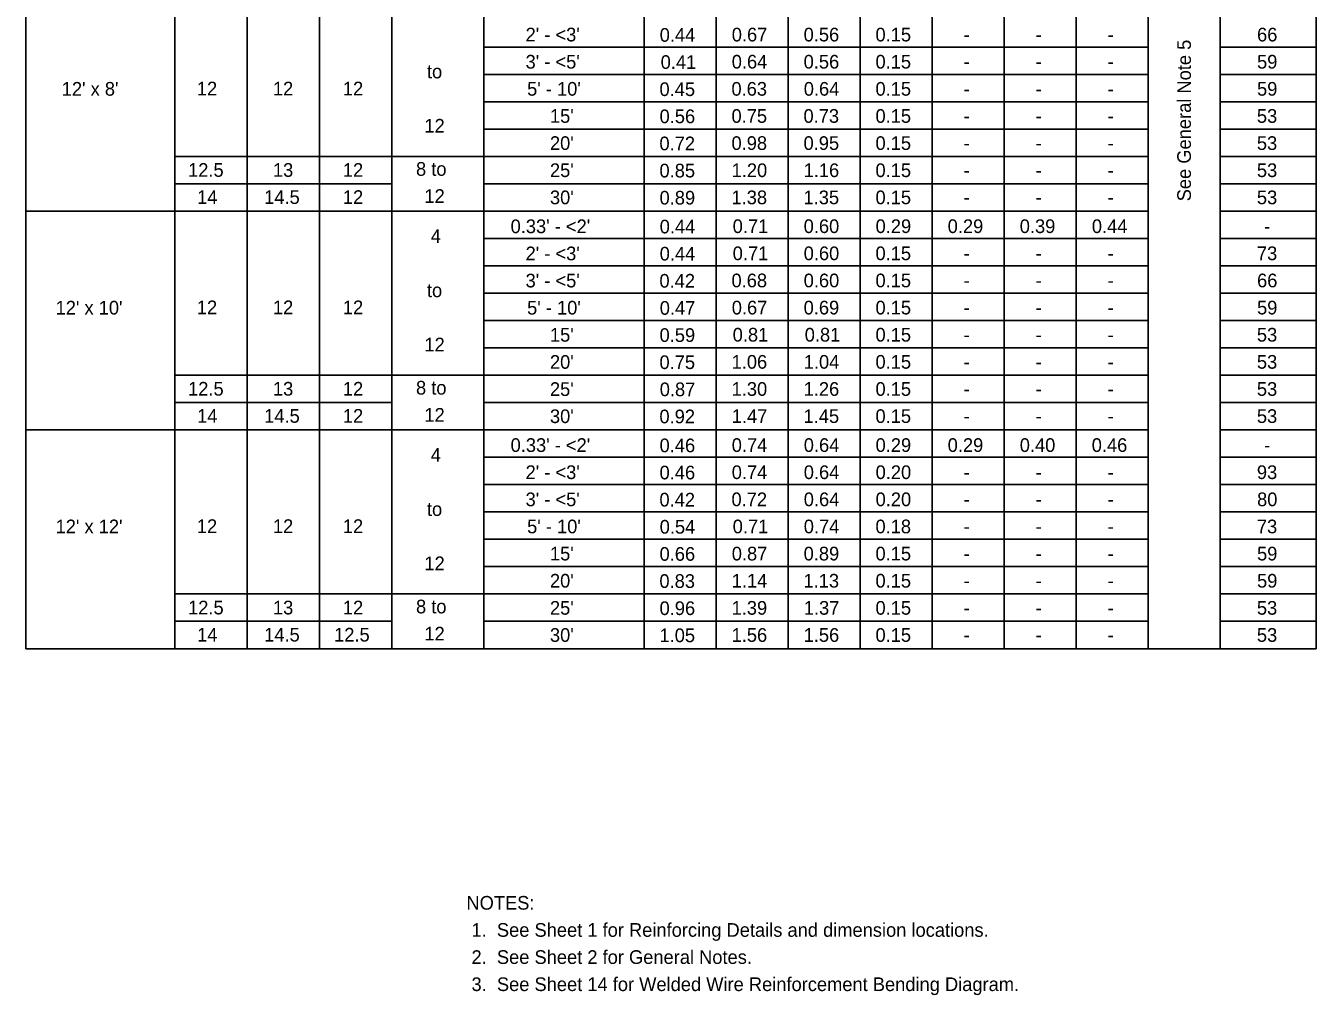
# Model space of a CAD drawing. Extents: x 10351.18 to 10353.4, y 76399.49 to 76400.59.
# Drawn here: x 10351.832 to 10352.427, y 76399.766 to 76400.212 of the extents above; entities that cross this region are included whole.
import ezdxf

# ---------------------------------------------------------------- set-up
doc = ezdxf.new("R2010")
doc.units = 0
doc.layers.add('AdhocPoint_dp', color=7, linetype='Continuous')
doc.layers.add('PlotBorder_dp', color=7, linetype='Continuous')

msp = doc.modelspace()

# ---------------------------------------------------------------- linework, layer by layer
at = {"layer": 'PlotBorder_dp'}
for p, q in [((10351.83244, 76400.49971), (10351.83244, 76399.92549)), ((10352.42718, 76400.49971), (10352.42718, 76399.92549)), ((10351.90108, 76400.47984), (10351.90108, 76399.92549)), ((10352.04352, 76400.47984), (10352.04352, 76399.92549)), ((10352.1174, 76400.47984), (10352.1174, 76399.92549)), ((10352.38299, 76400.47984), (10352.38299, 76399.92549)), ((10351.93444, 76400.46724), (10351.93444, 76399.92549)), ((10351.9678, 76400.46724), (10351.9678, 76399.92549)), ((10352.00116, 76400.46724), (10352.00116, 76399.92549)), ((10352.1506, 76400.44209), (10352.1506, 76399.92549)), ((10352.1838, 76400.44209), (10352.1838, 76399.92549)), ((10352.217, 76400.44209), (10352.217, 76399.92549)), ((10352.2502, 76400.44209), (10352.2502, 76399.92549)), ((10352.28339, 76400.44209), (10352.28339, 76399.92549)), ((10352.28339, 76400.44209), (10352.28339, 76399.92549)), ((10352.31659, 76400.44209), (10352.31659, 76399.92549)), ((10352.34979, 76400.44209), (10352.34979, 76399.92549)), ((10352.04352, 76400.20269), (10352.34979, 76400.20269)), ((10352.38299, 76400.20269), (10352.42718, 76400.20269)), ((10352.04352, 76400.19009), (10352.34979, 76400.19009)), ((10352.38299, 76400.19009), (10352.42718, 76400.19009)), ((10352.04352, 76400.17749), (10352.34979, 76400.17749)), ((10352.38299, 76400.17749), (10352.42718, 76400.17749)), ((10352.04352, 76400.16489), (10352.34979, 76400.16489)), ((10352.38299, 76400.16489), (10352.42718, 76400.16489)), ((10352.04352, 76400.15229), (10351.90108, 76400.15229)), ((10352.04352, 76400.15229), (10352.34979, 76400.15229)), ((10352.38299, 76400.15229), (10352.42718, 76400.15229)), ((10352.00116, 76400.13969), (10351.90108, 76400.13969)), ((10352.04352, 76400.13969), (10352.34979, 76400.13969)), ((10352.38299, 76400.13969), (10352.42718, 76400.13969)), ((10351.83244, 76400.12709), (10352.34979, 76400.12709)), ((10352.04414, 76400.12709), (10352.11631, 76400.12709)), ((10352.38299, 76400.12709), (10352.42718, 76400.12709)), ((10352.04352, 76400.11449), (10352.34979, 76400.11449)), ((10352.38299, 76400.11449), (10352.42718, 76400.11449)), ((10352.04352, 76400.10189), (10352.34979, 76400.10189)), ((10352.38299, 76400.10189), (10352.42718, 76400.10189)), ((10352.04352, 76400.08929), (10352.34979, 76400.08929)), ((10352.38299, 76400.08929), (10352.42718, 76400.08929)), ((10352.04352, 76400.07669), (10352.34979, 76400.07669)), ((10352.38299, 76400.07669), (10352.42718, 76400.07669)), ((10352.04352, 76400.06409), (10352.34979, 76400.06409)), ((10352.38299, 76400.06409), (10352.42718, 76400.06409)), ((10352.04352, 76400.05149), (10351.90108, 76400.05149)), ((10352.04352, 76400.05149), (10352.34979, 76400.05149)), ((10352.38299, 76400.05149), (10352.42718, 76400.05149)), ((10352.00116, 76400.03889), (10351.90108, 76400.03889)), ((10352.04352, 76400.03889), (10352.34979, 76400.03889)), ((10352.38299, 76400.03889), (10352.42718, 76400.03889)), ((10351.83244, 76400.02629), (10352.34979, 76400.02629)), ((10352.04414, 76400.02629), (10352.11631, 76400.02629)), ((10352.38299, 76400.02629), (10352.42718, 76400.02629)), ((10352.04352, 76400.01369), (10352.34979, 76400.01369)), ((10352.38299, 76400.01369), (10352.42718, 76400.01369)), ((10352.04352, 76400.00109), (10352.34979, 76400.00109)), ((10352.38299, 76400.00109), (10352.42718, 76400.00109)), ((10352.04352, 76399.98849), (10352.34979, 76399.98849)), ((10352.38299, 76399.98849), (10352.42718, 76399.98849)), ((10352.04352, 76399.97589), (10352.34979, 76399.97589)), ((10352.38299, 76399.97589), (10352.42718, 76399.97589)), ((10352.04352, 76399.96329), (10352.34979, 76399.96329)), ((10352.38299, 76399.96329), (10352.42718, 76399.96329)), ((10352.04352, 76399.95069), (10351.90108, 76399.95069)), ((10352.04352, 76399.95069), (10352.34979, 76399.95069)), ((10352.38299, 76399.95069), (10352.42718, 76399.95069)), ((10352.00116, 76399.93809), (10351.90108, 76399.93809)), ((10352.04352, 76399.93809), (10352.34979, 76399.93809)), ((10352.38299, 76399.93809), (10352.42718, 76399.93809)), ((10351.83244, 76399.92549), (10352.42718, 76399.92549)), ((10352.04414, 76399.92549), (10352.11631, 76399.92549)), ((10352.04414, 76399.92549), (10352.11631, 76399.92549)), ((10352.04414, 76399.92549), (10352.11631, 76399.92549))]:
    msp.add_line(p, q, dxfattribs=at)

# ---------------------------------------------------------------- texts
at = {"layer": 'AdhocPoint_dp'}
msp.add_text('See General Note 5', height=0.0063, rotation=90, dxfattribs=at).set_placement((10352.36944, 76400.13159))
at = {"layer": 'PlotBorder_dp'}
for s, p in [("2' - <3'", (10352.06278, 76400.20526)), ('0.44', (10352.1246, 76400.2051)), ('0.67', (10352.15782, 76400.20526)), ('0.56', (10352.19094, 76400.20526)), ('0.15', (10352.22406, 76400.20526)), ('66', (10352.39992, 76400.20526)), ('-', (10352.26467, 76400.20526)), ('-', (10352.29788, 76400.20526)), ('-', (10352.33106, 76400.20526)), ("3' - <5'", (10352.06278, 76400.19276)), ('0.41', (10352.12504, 76400.1926)), ('0.64', (10352.1578, 76400.19276)), ('0.56', (10352.19094, 76400.19276)), ('0.15', (10352.22406, 76400.19276)), ('59', (10352.39992, 76400.19276)), ('to', (10352.01732, 76400.18825)), ('-', (10352.26467, 76400.19276)), ('-', (10352.29788, 76400.19276)), ('-', (10352.33106, 76400.19276)), ("12' x 8'", (10351.849, 76400.18026)), ('12', (10351.91127, 76400.18038)), ('12', (10351.94634, 76400.18038)), ('12', (10351.97858, 76400.18038)), ("5' - 10'", (10352.06349, 76400.18026)), ('0.45', (10352.1245, 76400.1801)), ('0.63', (10352.15767, 76400.18026)), ('0.64', (10352.191, 76400.18026)), ('0.15', (10352.22406, 76400.18026)), ('59', (10352.39992, 76400.18026)), ('-', (10352.26467, 76400.18026)), ('-', (10352.29788, 76400.18026)), ('-', (10352.33106, 76400.18026)), ("15'", (10352.07401, 76400.16776)), ('0.56', (10352.12454, 76400.1676)), ('0.75', (10352.1577, 76400.16776)), ('0.73', (10352.19087, 76400.16776)), ('0.15', (10352.22406, 76400.16776)), ('53', (10352.39985, 76400.16776)), ('12', (10352.01615, 76400.16325)), ('-', (10352.26467, 76400.16776)), ('-', (10352.29788, 76400.16776)), ('-', (10352.33106, 76400.16776)), ("20'", (10352.07401, 76400.15526)), ('0.98', (10352.15769, 76400.15526)), ('0.95', (10352.1909, 76400.15526)), ('0.15', (10352.22406, 76400.15526)), ('53', (10352.39985, 76400.15526)), ('0.72', (10352.12448, 76400.1551)), ('-', (10352.26467, 76400.15526)), ('-', (10352.29788, 76400.15526)), ('-', (10352.33106, 76400.15526)), ('8 to', (10352.01228, 76400.14336)), ('12.5', (10351.90723, 76400.14288)), ('13', (10351.94634, 76400.14288)), ('12', (10351.97858, 76400.14288)), ("25'", (10352.07401, 76400.14276)), ('0.85', (10352.1245, 76400.1426)), ('1.20', (10352.15775, 76400.14276)), ('1.16', (10352.19094, 76400.14276)), ('0.15', (10352.22406, 76400.14276)), ('-', (10352.26467, 76400.14276)), ('-', (10352.29788, 76400.14276)), ('-', (10352.33106, 76400.14276)), ('53', (10352.39985, 76400.14276)), ('14', (10351.9114, 76400.13038)), ('14.5', (10351.9423, 76400.13038)), ('12', (10351.97858, 76400.13038)), ('12', (10352.01615, 76400.13086)), ("30'", (10352.07401, 76400.13026)), ('0.89', (10352.12454, 76400.1301)), ('1.38', (10352.15769, 76400.13026)), ('1.35', (10352.1909, 76400.13026)), ('0.15', (10352.22406, 76400.13026)), ('-', (10352.26467, 76400.13026)), ('-', (10352.29788, 76400.13026)), ('-', (10352.33106, 76400.13026)), ('53', (10352.39985, 76400.13026)), ("0.33' - <2'", (10352.05588, 76400.11693)), ('0.44', (10352.1246, 76400.11682)), ('0.71', (10352.15824, 76400.11698)), ('0.60', (10352.19096, 76400.11698)), ('0.29', (10352.2241, 76400.11698)), ('0.29', (10352.25733, 76400.11698)), ('0.39', (10352.29054, 76400.11698)), ('0.44', (10352.32378, 76400.11698)), ('4', (10352.0191, 76400.11245)), ('-', (10352.40319, 76400.11698)), ("2' - <3'", (10352.06278, 76400.10443)), ('0.44', (10352.1246, 76400.10432)), ('0.71', (10352.15824, 76400.10448)), ('0.60', (10352.19096, 76400.10448)), ('0.15', (10352.22406, 76400.10448)), ('73', (10352.39985, 76400.10448)), ('-', (10352.26467, 76400.10448)), ('-', (10352.29788, 76400.10448)), ('-', (10352.33106, 76400.10448)), ("3' - <5'", (10352.06278, 76400.09193)), ('0.42', (10352.12448, 76400.09182)), ('0.68', (10352.15769, 76400.09198)), ('0.60', (10352.19096, 76400.09198)), ('0.15', (10352.22406, 76400.09198)), ('66', (10352.39992, 76400.09198)), ('to', (10352.01732, 76400.08745)), ('-', (10352.26467, 76400.09198)), ('-', (10352.29788, 76400.09198)), ('-', (10352.33106, 76400.09198)), ("12' x 10'", (10351.84617, 76400.07943)), ('12', (10351.91127, 76400.07958)), ('12', (10351.94634, 76400.07958)), ('12', (10351.97858, 76400.07958)), ("5' - 10'", (10352.06349, 76400.07943)), ('0.47', (10352.12462, 76400.07932)), ('0.67', (10352.15782, 76400.07948)), ('0.69', (10352.19094, 76400.07948)), ('0.15', (10352.22406, 76400.07948)), ('59', (10352.39992, 76400.07948)), ('-', (10352.26467, 76400.07948)), ('-', (10352.29788, 76400.07948)), ('-', (10352.33106, 76400.07948)), ("15'", (10352.07401, 76400.06693)), ('0.59', (10352.12454, 76400.06682)), ('0.81', (10352.15824, 76400.06698)), ('0.81', (10352.19144, 76400.06698)), ('0.15', (10352.22406, 76400.06698)), ('53', (10352.39985, 76400.06698)), ('12', (10352.01615, 76400.06245)), ('-', (10352.26467, 76400.06698)), ('-', (10352.29788, 76400.06698)), ('-', (10352.33106, 76400.06698)), ("20'", (10352.07401, 76400.05443)), ('0.75', (10352.1245, 76400.05432)), ('1.06', (10352.15774, 76400.05448)), ('1.04', (10352.191, 76400.05448)), ('0.15', (10352.22406, 76400.05448)), ('53', (10352.39985, 76400.05448)), ('-', (10352.26467, 76400.05448)), ('-', (10352.29788, 76400.05448)), ('-', (10352.33106, 76400.05448)), ('8 to', (10352.01228, 76400.04256)), ('12.5', (10351.90723, 76400.04208)), ('13', (10351.94634, 76400.04208)), ('12', (10351.97858, 76400.04208)), ("25'", (10352.07401, 76400.04193)), ('0.87', (10352.12462, 76400.04182)), ('1.30', (10352.15775, 76400.04198)), ('1.26', (10352.19094, 76400.04198)), ('0.15', (10352.22406, 76400.04198)), ('-', (10352.26467, 76400.04198)), ('-', (10352.29788, 76400.04198)), ('-', (10352.33106, 76400.04198)), ('53', (10352.39985, 76400.04198)), ('14', (10351.9114, 76400.02958)), ('14.5', (10351.9423, 76400.02958)), ('12', (10351.97858, 76400.02958)), ('12', (10352.01615, 76400.03006)), ("30'", (10352.07401, 76400.02943)), ('0.92', (10352.12448, 76400.02932)), ('1.47', (10352.15782, 76400.02948)), ('1.45', (10352.1909, 76400.02948)), ('0.15', (10352.22406, 76400.02948)), ('-', (10352.26467, 76400.02948)), ('-', (10352.29788, 76400.02948)), ('-', (10352.33106, 76400.02948)), ('53', (10352.39985, 76400.02948)), ("0.33' - <2'", (10352.05588, 76400.01614)), ('0.46', (10352.12454, 76400.01599)), ('0.74', (10352.1578, 76400.01614)), ('0.64', (10352.191, 76400.01614)), ('0.29', (10352.2241, 76400.01614)), ('0.29', (10352.25733, 76400.01614)), ('0.40', (10352.29055, 76400.01614)), ('0.46', (10352.32372, 76400.01614)), ('-', (10352.40319, 76400.01614)), ('4', (10352.0191, 76400.01165)), ("2' - <3'", (10352.06278, 76400.00364)), ('0.46', (10352.12454, 76400.00349)), ('0.74', (10352.1578, 76400.00364)), ('0.64', (10352.191, 76400.00364)), ('0.20', (10352.22411, 76400.00364)), ('93', (10352.39985, 76400.00364)), ('-', (10352.26467, 76400.00364)), ('-', (10352.29788, 76400.00364)), ('-', (10352.33106, 76400.00364)), ("3' - <5'", (10352.06278, 76399.99114)), ('0.42', (10352.12448, 76399.99099)), ('0.72', (10352.15768, 76399.99114)), ('0.64', (10352.191, 76399.99114)), ('0.20', (10352.22411, 76399.99114)), ('80', (10352.39993, 76399.99114)), ('to', (10352.01732, 76399.98665)), ('-', (10352.26467, 76399.99114)), ('-', (10352.29788, 76399.99114)), ('-', (10352.33106, 76399.99114)), ("12' x 12'", (10351.84617, 76399.97864)), ('12', (10351.91127, 76399.97878)), ('12', (10351.94634, 76399.97878)), ('12', (10351.97858, 76399.97878)), ("5' - 10'", (10352.06349, 76399.97864)), ('0.54', (10352.1246, 76399.97849)), ('0.71', (10352.15824, 76399.97864)), ('0.74', (10352.191, 76399.97864)), ('0.18', (10352.22405, 76399.97864)), ('73', (10352.39985, 76399.97864)), ('-', (10352.26467, 76399.97864)), ('-', (10352.29788, 76399.97864)), ('-', (10352.33106, 76399.97864)), ("15'", (10352.07401, 76399.96614)), ('0.66', (10352.12454, 76399.96599)), ('0.87', (10352.15782, 76399.96614)), ('0.89', (10352.19094, 76399.96614)), ('0.15', (10352.22406, 76399.96614)), ('59', (10352.39992, 76399.96614)), ('12', (10352.01615, 76399.96165)), ('-', (10352.26467, 76399.96614)), ('-', (10352.29788, 76399.96614)), ('-', (10352.33106, 76399.96614)), ("20'", (10352.07401, 76399.95364)), ('0.83', (10352.12447, 76399.95349)), ('1.14', (10352.1578, 76399.95364)), ('1.13', (10352.19087, 76399.95364)), ('0.15', (10352.22406, 76399.95364)), ('59', (10352.39992, 76399.95364)), ('-', (10352.26467, 76399.95364)), ('-', (10352.29788, 76399.95364)), ('-', (10352.33106, 76399.95364)), ('12.5', (10351.90723, 76399.94128)), ('13', (10351.94634, 76399.94128)), ('12', (10351.97858, 76399.94128)), ('8 to', (10352.01228, 76399.94176)), ("25'", (10352.07401, 76399.94114)), ('1.39', (10352.15774, 76399.94114)), ('1.37', (10352.19102, 76399.94114)), ('0.15', (10352.22406, 76399.94114)), ('53', (10352.39985, 76399.94114)), ('0.96', (10352.12454, 76399.94099)), ('-', (10352.26467, 76399.94114)), ('-', (10352.29788, 76399.94114)), ('-', (10352.33106, 76399.94114)), ('12', (10352.01615, 76399.92926)), ('14', (10351.9114, 76399.92878)), ('14.5', (10351.9423, 76399.92878)), ('12.5', (10351.97453, 76399.92878)), ("30'", (10352.07401, 76399.92864)), ('1.05', (10352.1245, 76399.92849)), ('1.56', (10352.15774, 76399.92864)), ('1.56', (10352.19094, 76399.92864)), ('0.15', (10352.22406, 76399.92864)), ('-', (10352.26467, 76399.92864)), ('-', (10352.29788, 76399.92864)), ('-', (10352.33106, 76399.92864)), ('53', (10352.39985, 76399.92864)), ('NOTES:', (10352.03552, 76399.80525)), (' 1.  See Sheet 1 for Reinforcing Details and dimension locations.', (10352.03552, 76399.79275)), (' 2.  See Sheet 2 for General Notes.', (10352.03552, 76399.78025)), (' 3.  See Sheet 14 for Welded Wire Reinforcement Bending Diagram.', (10352.03552, 76399.76775))]:
    msp.add_text(s, height=0.0063, dxfattribs=at).set_placement(p)

doc.saveas('drawing.dxf')
